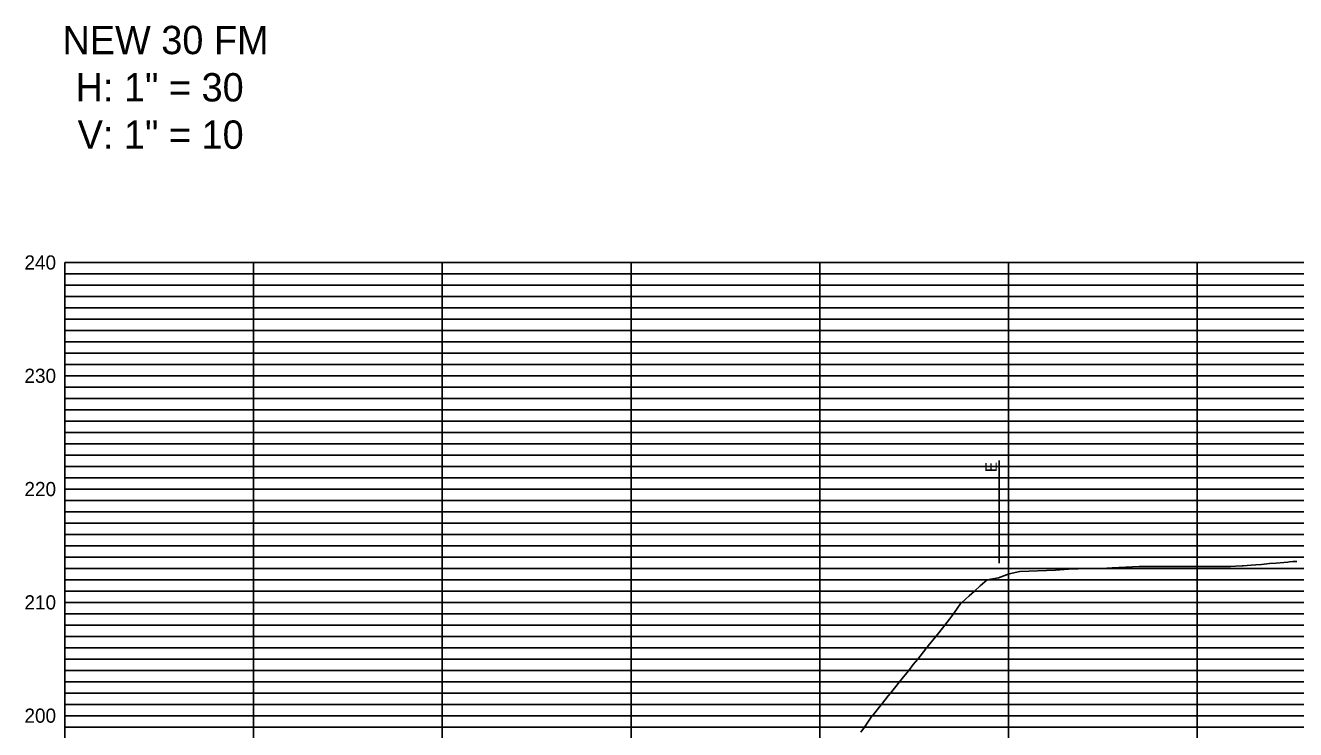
# Model space of a CAD drawing. Extents: x 1961446 to 1965364, y 798002 to 798458.
# Drawn here: x 1964691.8 to 1965028.3, y 798189.8 to 798376.3 of the extents above; entities that cross this region are included whole.
import ezdxf

# ---------------------------------------------------------------- set-up
doc = ezdxf.new("R2010")
doc.units = 0
for name, color, linetype in [('_C3D-PRSR-ANNO', 7, 'Continuous'), ('C-ANNO-NPLT', 7, 'Continuous'), ('C-ANNO-SUBT', 7, 'Continuous'), ('C-GRID-MEDI', 7, 'Continuous'), ('C-GRID-THIN', 7, 'Continuous'), ('C-PROF-EXST', 7, 'Continuous'), ('C-UTIL-FITT-ANNO', 7, 'Continuous')]:
    doc.layers.add(name, color=color, linetype=linetype)

msp = doc.modelspace()

# ---------------------------------------------------------------- linework, layer by layer
at = {"layer": '_C3D-PRSR-ANNO'}
msp.add_lwpolyline([(1964949.78, 798233.84), (1964949.78, 798261.08)], dxfattribs=at)
at = {"layer": 'C-GRID-MEDI'}
for points in [[(1964702.28, 798313.48), (1964752.28, 798313.48)], [(1964702.28, 798007.48), (1964702.28, 798313.48)], [(1964702.28, 798007.48), (1964702.28, 798313.48)], [(1964702.28, 798313.48), (1965352.28, 798313.48)], [(1964752.28, 798313.48), (1965283.11, 798313.48)], [(1964752.28, 798007.48), (1964752.28, 798313.48)], [(1964802.28, 798007.48), (1964802.28, 798313.48)], [(1964852.28, 798007.48), (1964852.28, 798313.48)], [(1964902.28, 798007.48), (1964902.28, 798313.48)], [(1964952.28, 798007.48), (1964952.28, 798313.48)], [(1965002.28, 798007.48), (1965002.28, 798313.48)], [(1964702.28, 798283.48), (1964752.28, 798283.48)], [(1964752.28, 798283.48), (1965283.11, 798283.48)], [(1964702.28, 798253.48), (1964752.28, 798253.48)], [(1964752.28, 798253.48), (1965283.11, 798253.48)], [(1964702.28, 798223.48), (1964752.28, 798223.48)], [(1964752.28, 798223.48), (1965283.11, 798223.48)], [(1964702.28, 798193.48), (1964752.28, 798193.48)], [(1964752.28, 798193.48), (1965283.11, 798193.48)]]:
    msp.add_lwpolyline(points, dxfattribs=at)
at = {"layer": 'C-GRID-THIN'}
for points in [[(1964702.28, 798310.48), (1964752.28, 798310.48)], [(1964752.28, 798310.48), (1965283.11, 798310.48)], [(1964702.28, 798307.48), (1964752.28, 798307.48)], [(1964752.28, 798307.48), (1965283.11, 798307.48)], [(1964702.28, 798304.48), (1964752.28, 798304.48)], [(1964752.28, 798304.48), (1965283.11, 798304.48)], [(1964702.28, 798301.48), (1964752.28, 798301.48)], [(1964702.28, 798298.48), (1964752.28, 798298.48)], [(1964752.28, 798301.48), (1965283.11, 798301.48)], [(1964752.28, 798298.48), (1965283.11, 798298.48)], [(1964702.28, 798295.48), (1964752.28, 798295.48)], [(1964752.28, 798295.48), (1965283.11, 798295.48)], [(1964702.28, 798292.48), (1964752.28, 798292.48)], [(1964752.28, 798292.48), (1965283.11, 798292.48)], [(1964702.28, 798289.48), (1964752.28, 798289.48)], [(1964752.28, 798289.48), (1965283.11, 798289.48)], [(1964702.28, 798286.48), (1964752.28, 798286.48)], [(1964752.28, 798286.48), (1965283.11, 798286.48)], [(1964702.28, 798280.48), (1964752.28, 798280.48)], [(1964752.28, 798280.48), (1965283.11, 798280.48)], [(1964702.28, 798277.48), (1964752.28, 798277.48)], [(1964752.28, 798277.48), (1965283.11, 798277.48)], [(1964702.28, 798274.48), (1964752.28, 798274.48)], [(1964702.28, 798271.48), (1964752.28, 798271.48)], [(1964752.28, 798274.48), (1965283.11, 798274.48)], [(1964752.28, 798271.48), (1965283.11, 798271.48)], [(1964702.28, 798268.48), (1964752.28, 798268.48)], [(1964752.28, 798268.48), (1965283.11, 798268.48)], [(1964702.28, 798265.48), (1964752.28, 798265.48)], [(1964752.28, 798265.48), (1965283.11, 798265.48)], [(1964702.28, 798262.48), (1964752.28, 798262.48)], [(1964752.28, 798262.48), (1965283.11, 798262.48)], [(1964702.28, 798259.48), (1964752.28, 798259.48)], [(1964752.28, 798259.48), (1965283.11, 798259.48)], [(1964702.28, 798256.48), (1964752.28, 798256.48)], [(1964752.28, 798256.48), (1965283.11, 798256.48)], [(1964702.28, 798250.48), (1964752.28, 798250.48)], [(1964752.28, 798250.48), (1965283.11, 798250.48)], [(1964702.28, 798247.48), (1964752.28, 798247.48)], [(1964702.28, 798244.48), (1964752.28, 798244.48)], [(1964752.28, 798247.48), (1965283.11, 798247.48)], [(1964752.28, 798244.48), (1965283.11, 798244.48)], [(1964702.28, 798241.48), (1964752.28, 798241.48)], [(1964752.28, 798241.48), (1965283.11, 798241.48)], [(1964702.28, 798238.48), (1964752.28, 798238.48)], [(1964752.28, 798238.48), (1965283.11, 798238.48)], [(1964702.28, 798235.48), (1964752.28, 798235.48)], [(1964752.28, 798235.48), (1965283.11, 798235.48)], [(1964702.28, 798232.48), (1964752.28, 798232.48)], [(1964752.28, 798232.48), (1965283.11, 798232.48)], [(1964702.28, 798229.48), (1964752.28, 798229.48)], [(1964752.28, 798229.48), (1965283.11, 798229.48)], [(1964702.28, 798226.48), (1964752.28, 798226.48)], [(1964752.28, 798226.48), (1965283.11, 798226.48)], [(1964702.28, 798220.48), (1964752.28, 798220.48)], [(1964702.28, 798217.48), (1964752.28, 798217.48)], [(1964752.28, 798220.48), (1965283.11, 798220.48)], [(1964752.28, 798217.48), (1965283.11, 798217.48)], [(1964702.28, 798214.48), (1964752.28, 798214.48)], [(1964752.28, 798214.48), (1965283.11, 798214.48)], [(1964702.28, 798211.48), (1964752.28, 798211.48)], [(1964752.28, 798211.48), (1965283.11, 798211.48)], [(1964702.28, 798208.48), (1964752.28, 798208.48)], [(1964752.28, 798208.48), (1965283.11, 798208.48)], [(1964702.28, 798205.48), (1964752.28, 798205.48)], [(1964752.28, 798205.48), (1965283.11, 798205.48)], [(1964702.28, 798202.48), (1964752.28, 798202.48)], [(1964752.28, 798202.48), (1965283.11, 798202.48)], [(1964702.28, 798199.48), (1964752.28, 798199.48)], [(1964752.28, 798199.48), (1965283.11, 798199.48)], [(1964702.28, 798196.48), (1964752.28, 798196.48)], [(1964752.28, 798196.48), (1965283.11, 798196.48)], [(1964702.28, 798190.48), (1964752.28, 798190.48)], [(1964752.28, 798190.48), (1965283.11, 798190.48)]]:
    msp.add_lwpolyline(points, dxfattribs=at)
at = {"layer": 'C-PROF-EXST'}
for points in [[(1965026.7, 798234.21), (1965027.62, 798234.28)], [(1965027.62, 798234.28), (1965028.63, 798234.36)], [(1964949.6, 798229.98), (1964952.45, 798231.02)], [(1964952.45, 798231.02), (1964955.27, 798231.7)], [(1964955.27, 798231.7), (1964964.76, 798232.06)], [(1964964.76, 798232.06), (1964968.13, 798232.31)], [(1964968.13, 798232.31), (1964973.41, 798232.48)], [(1964973.41, 798232.48), (1964976.75, 798232.49)], [(1964976.75, 798232.49), (1964976.9, 798232.49)], [(1964976.9, 798232.49), (1964979.7, 798232.65)], [(1964979.7, 798232.65), (1964986.86, 798233.04)], [(1964986.86, 798233.04), (1964993.01, 798233.01)], [(1964993.01, 798233.01), (1964993.2, 798233)], [(1964993.2, 798233), (1964993.5, 798233)], [(1964993.5, 798233), (1964994.05, 798233)], [(1964994.05, 798233), (1964994.07, 798233)], [(1964994.07, 798233), (1965000.76, 798233)], [(1965000.76, 798233), (1965001.53, 798232.99)], [(1965001.53, 798232.99), (1965001.91, 798232.99)], [(1965001.91, 798232.99), (1965002.64, 798232.99)], [(1965002.64, 798232.99), (1965003.37, 798233)], [(1965003.37, 798233), (1965003.46, 798232.99)], [(1965003.46, 798232.99), (1965005.98, 798232.99)], [(1965005.98, 798232.99), (1965007.99, 798232.97)], [(1965007.99, 798232.97), (1965010.04, 798232.98)], [(1965010.04, 798232.98), (1965010.1, 798232.98)], [(1965010.1, 798232.98), (1965010.24, 798232.98)], [(1965010.24, 798232.98), (1965010.39, 798232.99)], [(1965010.39, 798232.99), (1965011.02, 798233.01)], [(1965011.02, 798233.01), (1965011.11, 798233.01)], [(1965011.11, 798233.01), (1965012.45, 798233.06)], [(1965012.45, 798233.06), (1965014.16, 798233.16)], [(1965014.16, 798233.16), (1965014.43, 798233.18)], [(1965014.43, 798233.18), (1965015.52, 798233.27)], [(1965015.52, 798233.27), (1965016.53, 798233.35)], [(1965016.53, 798233.35), (1965017.78, 798233.44)], [(1965017.78, 798233.44), (1965019.31, 798233.56)], [(1965019.31, 798233.56), (1965021.42, 798233.75)], [(1965021.42, 798233.75), (1965023.15, 798233.9)], [(1965023.15, 798233.9), (1965025.23, 798234.07)], [(1965025.23, 798234.07), (1965026.25, 798234.17)], [(1965026.25, 798234.17), (1965026.7, 798234.21)], [(1964943.24, 798226.48), (1964944.78, 798227.86)], [(1964944.78, 798227.86), (1964946.6, 798229.48)], [(1964946.6, 798229.48), (1964949.6, 798229.98)], [(1964939.88, 798223.48), (1964941.85, 798225.25)], [(1964941.85, 798225.25), (1964943.24, 798226.48)], [(1964937.71, 798220.48), (1964939.62, 798223.25)], [(1964939.62, 798223.25), (1964939.88, 798223.48)], [(1964933.78, 798215.46), (1964935.39, 798217.48)], [(1964935.39, 798217.48), (1964936.6, 798219.08)], [(1964936.6, 798219.08), (1964937.71, 798220.48)], [(1964931, 798211.97), (1964933, 798214.48)], [(1964933, 798214.48), (1964933.78, 798215.46)], [(1964928.22, 798208.48), (1964930.37, 798211.18)], [(1964930.37, 798211.18), (1964930.61, 798211.48)], [(1964930.61, 798211.48), (1964931, 798211.97)], [(1964927.05, 798207.02), (1964928.22, 798208.48)], [(1964924.46, 798203.77), (1964925.83, 798205.48)], [(1964925.83, 798205.48), (1964927.05, 798207.02)], [(1964921, 798199.48), (1964922.1, 798200.81)], [(1964922.1, 798200.81), (1964923.44, 798202.48)], [(1964923.44, 798202.48), (1964924.46, 798203.77)], [(1964918.61, 798196.48), (1964920.42, 798198.76)], [(1964920.42, 798198.76), (1964921, 798199.48)], [(1964916.2, 798193.48), (1964918.13, 798195.88)], [(1964918.13, 798195.88), (1964918.61, 798196.48)], [(1964913.14, 798189.15), (1964914.08, 798190.48)], [(1964914.08, 798190.48), (1964915.01, 798191.8)], [(1964915.01, 798191.8), (1964916.1, 798193.35)], [(1964916.1, 798193.35), (1964916.18, 798193.45)], [(1964916.18, 798193.45), (1964916.2, 798193.48)]]:
    msp.add_lwpolyline(points, dxfattribs=at)

# ---------------------------------------------------------------- texts
at = {"layer": 'C-ANNO-NPLT'}
for s, p in [('NEW 30 FM', (1964701.64, 798368.66)), ('H: 1" = 30', (1964705.12, 798356.14)), ('V: 1" = 10', (1964705.67, 798343.61))]:
    msp.add_text(s, height=7.5, rotation=360, dxfattribs=at).set_placement(p)
at = {"layer": 'C-ANNO-SUBT'}
for s, p in [('240', (1964691.58, 798311.63)), ('230', (1964691.58, 798281.63)), ('220', (1964691.58, 798251.63)), ('210', (1964691.58, 798221.63)), ('200', (1964691.58, 798191.63))]:
    msp.add_text(s, height=3.75, rotation=360, dxfattribs=at).set_placement(p)
at = {"layer": 'C-UTIL-FITT-ANNO'}
msp.add_text('E ', height=3, rotation=90, dxfattribs=at).set_placement((1964949.17, 798257.99))

doc.saveas('drawing.dxf')
